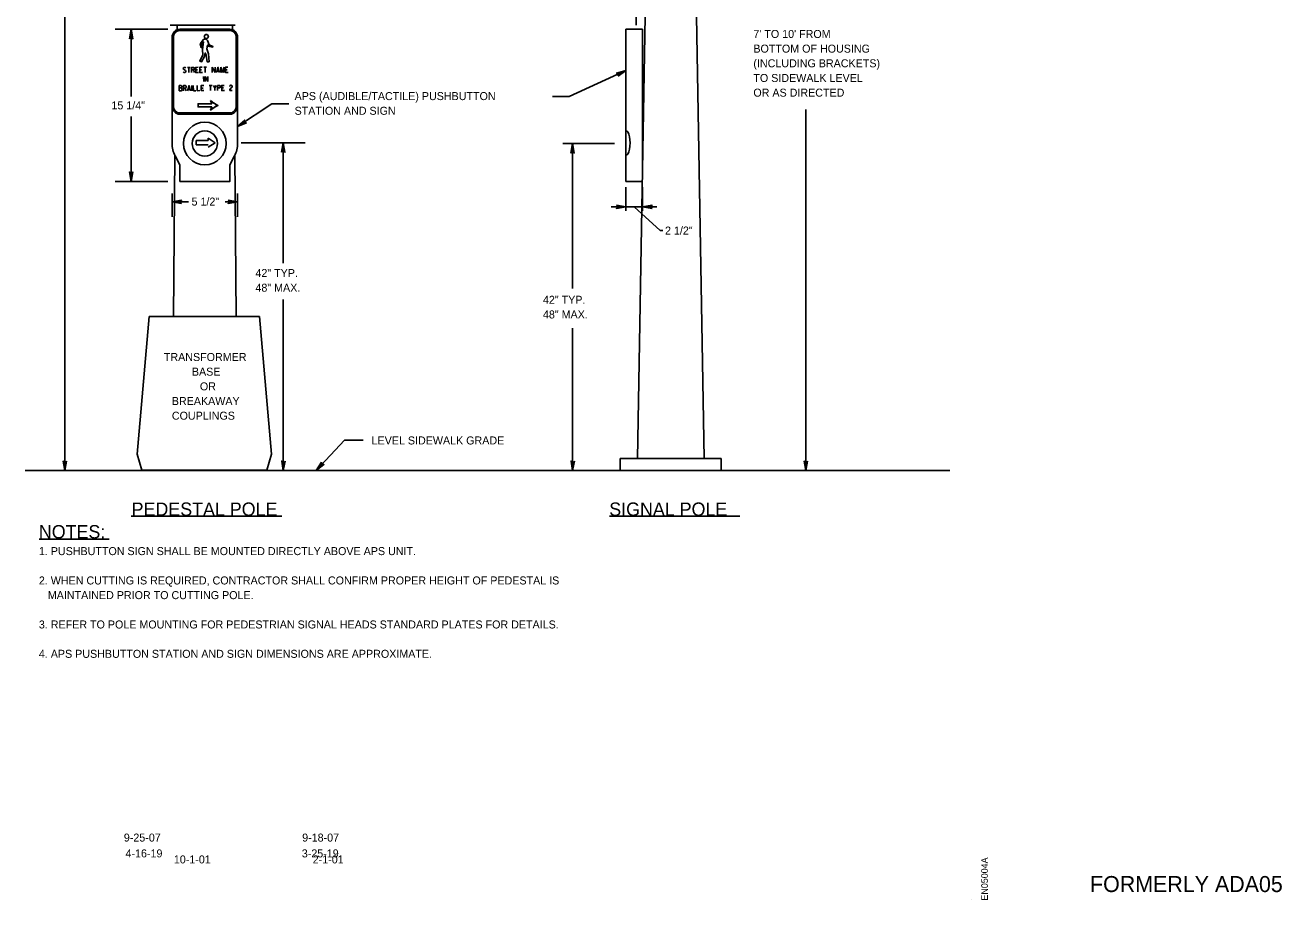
# Model space of a CAD drawing. Extents: x 12.4 to 21.9, y 5.3 to 15.4.
# Drawn here: x 12.52 to 21.94, y 5.33 to 11.89 of the extents above; entities that cross this region are included whole.
import ezdxf

# ---------------------------------------------------------------- set-up
doc = ezdxf.new("R2010")
doc.units = 0
for name, color, linetype in [('APPROVAL-OLD', 7, 'Continuous'), ('DETL-DIMS', 7, 'Continuous'), ('DETL-LINE', 7, 'Continuous'), ('DETL-NOTE', 7, 'Continuous'), ('DETL-TITL', 7, 'Continuous'), ('EN', 7, 'Continuous'), ('SIGN-FACE_P', 7, 'Continuous'), ('TTLB-TEXT', 7, 'Continuous')]:
    doc.layers.add(name, color=color, linetype=linetype)

msp = doc.modelspace()

# ---------------------------------------------------------------- linework, layer by layer
at = {"layer": 'DETL-DIMS'}
for p, q in [((12.8183, 12.1275), (12.8183, 8.549)), ((13.5893, 11.8579), (13.1959, 11.8579)), ((13.3153, 11.8579), (13.3023, 11.7865)), ((13.3023, 11.7865), (13.315, 11.7999)), ((13.315, 11.7999), (13.3275, 11.7863)), ((13.3153, 11.8579), (13.3275, 11.7863)), ((13.3153, 11.8579), (13.3153, 11.3531)), ((17.0236, 11.5479), (16.5976, 11.3538)), ((17.0236, 11.5479), (16.9534, 11.5293)), ((16.971, 11.5236), (16.9534, 11.5293)), ((17.0236, 11.5479), (16.9642, 11.5065)), ((16.9642, 11.5065), (16.971, 11.5236)), ((16.4721, 11.3538), (16.5976, 11.3538)), ((14.1129, 11.1281), (14.3704, 11.2982)), ((14.4959, 11.2982), (14.3704, 11.2982)), ((18.3716, 11.2568), (18.3716, 8.549)), ((13.3153, 11.2049), (13.3153, 10.7177)), ((14.1129, 11.1281), (14.1659, 11.1778)), ((14.1129, 11.1281), (14.1795, 11.1566)), ((14.1614, 11.1598), (14.1659, 11.1778)), ((14.1795, 11.1566), (14.1614, 11.1598)), ((14.6201, 11.0075), (14.1396, 11.0075)), ((14.4553, 11.0075), (14.4423, 10.9361)), ((14.4423, 10.9361), (14.455, 10.9495)), ((14.455, 10.9495), (14.4675, 10.9359)), ((14.4553, 11.0075), (14.4675, 10.9359)), ((14.4553, 11.0075), (14.4553, 10.1054)), ((16.9386, 11.0011), (16.5504, 11.0011)), ((16.6239, 11.0011), (16.6109, 10.9297)), ((16.6109, 10.9297), (16.6236, 10.9431)), ((16.6236, 10.9431), (16.6361, 10.9295)), ((16.6239, 11.0011), (16.6239, 9.9149)), ((16.6239, 11.0011), (16.6361, 10.9295)), ((13.3153, 10.7177), (13.3031, 10.7893)), ((13.3156, 10.7757), (13.3031, 10.7893)), ((13.3153, 10.7177), (13.3283, 10.7891)), ((13.3283, 10.7891), (13.3156, 10.7757)), ((13.5893, 10.7177), (13.1959, 10.7177)), ((17.0236, 10.6744), (17.0236, 10.4972)), ((17.1482, 10.6744), (17.1482, 10.4972)), ((13.6215, 10.6271), (13.6215, 10.453)), ((13.6215, 10.5643), (13.6931, 10.5765)), ((13.6215, 10.5643), (13.7457, 10.5643)), ((13.6215, 10.5643), (13.6929, 10.5513)), ((13.6795, 10.564), (13.6931, 10.5765)), ((13.6929, 10.5513), (13.6795, 10.564)), ((14.0203, 10.5643), (14.1129, 10.5643)), ((14.0549, 10.5646), (14.0413, 10.5521)), ((14.1129, 10.5643), (14.0413, 10.5521)), ((14.1129, 10.5643), (14.0415, 10.5773)), ((14.0415, 10.5773), (14.0549, 10.5646)), ((14.1129, 10.6271), (14.1129, 10.453)), ((16.9137, 10.5271), (17.2552, 10.5271)), ((16.9656, 10.5274), (16.952, 10.5149)), ((17.0236, 10.5271), (16.952, 10.5149)), ((17.0236, 10.5271), (16.9522, 10.5401)), ((16.9522, 10.5401), (16.9656, 10.5274)), ((17.2789, 10.3498), (17.0859, 10.5271)), ((17.1482, 10.5271), (17.2198, 10.5393)), ((17.1482, 10.5271), (17.2196, 10.5141)), ((17.2062, 10.5268), (17.2198, 10.5393)), ((17.2196, 10.5141), (17.2062, 10.5268)), ((17.2995, 10.3498), (17.2789, 10.3498)), ((14.4553, 9.8317), (14.4553, 8.549)), ((16.6239, 9.6167), (16.6239, 8.549)), ((14.9142, 8.7772), (14.702, 8.5511)), ((14.9143, 8.7772), (15.0537, 8.7772)), ((12.8183, 8.549), (12.8061, 8.6206)), ((12.8186, 8.607), (12.8061, 8.6206)), ((12.8183, 8.549), (12.8313, 8.6204)), ((12.8313, 8.6204), (12.8186, 8.607)), ((14.4553, 8.549), (14.4431, 8.6206)), ((14.4556, 8.607), (14.4431, 8.6206)), ((14.4553, 8.549), (14.4683, 8.6204)), ((14.4683, 8.6204), (14.4556, 8.607)), ((14.702, 8.551), (14.7414, 8.612)), ((14.702, 8.551), (14.7599, 8.5949)), ((14.7414, 8.612), (14.7415, 8.5935)), ((14.7415, 8.5935), (14.7599, 8.5949)), ((16.6239, 8.549), (16.6117, 8.6206)), ((16.6242, 8.607), (16.6117, 8.6206)), ((16.6239, 8.549), (16.6369, 8.6204)), ((16.6369, 8.6204), (16.6242, 8.607)), ((18.3716, 8.549), (18.3594, 8.6206)), ((18.3719, 8.607), (18.3594, 8.6206)), ((18.3716, 8.549), (18.3846, 8.6204)), ((18.3846, 8.6204), (18.3719, 8.607))]:
    msp.add_line(p, q, dxfattribs=at)
for points in [[(13.3023, 11.7865), (13.3153, 11.8579), (13.3275, 11.7863), (13.315, 11.7999)], [(16.9642, 11.5065), (17.0236, 11.5479), (16.9534, 11.5293), (16.971, 11.5236)], [(14.1795, 11.1566), (14.1129, 11.1281), (14.1659, 11.1778), (14.1614, 11.1598)], [(14.4423, 10.9361), (14.4553, 11.0075), (14.4675, 10.9359), (14.455, 10.9495)], [(16.6109, 10.9297), (16.6239, 11.0011), (16.6361, 10.9295), (16.6236, 10.9431)], [(13.3283, 10.7891), (13.3153, 10.7177), (13.3031, 10.7893), (13.3156, 10.7757)], [(13.6929, 10.5513), (13.6215, 10.5643), (13.6931, 10.5765), (13.6795, 10.564)], [(14.0415, 10.5773), (14.1129, 10.5643), (14.0413, 10.5521), (14.0549, 10.5646)], [(16.9522, 10.5401), (17.0236, 10.5271), (16.952, 10.5149), (16.9656, 10.5274)], [(17.2196, 10.5141), (17.1482, 10.5271), (17.2198, 10.5393), (17.2062, 10.5268)], [(12.8313, 8.6204), (12.8183, 8.549), (12.8061, 8.6206), (12.8186, 8.607)], [(14.4683, 8.6204), (14.4553, 8.549), (14.4431, 8.6206), (14.4556, 8.607)], [(14.7414, 8.612), (14.702, 8.551), (14.7599, 8.5949), (14.7415, 8.5935)], [(16.6369, 8.6204), (16.6239, 8.549), (16.6117, 8.6206), (16.6242, 8.607)], [(18.3846, 8.6204), (18.3716, 8.549), (18.3594, 8.6206), (18.3719, 8.607)]]:
    msp.add_lwpolyline(points, close=True, dxfattribs=at)
at = {"layer": 'DETL-LINE'}
for p, q in [((17.1109, 8.6403), (17.1939, 13.5402)), ((17.609, 8.6403), (17.526, 13.5402)), ((17.1001, 11.8893), (17.1001, 13.1019)), ((13.661, 11.8893), (13.6602, 11.8545)), ((14.0742, 11.8545), (14.0735, 11.8893)), ((17.0236, 11.2379), (17.0236, 11.8579)), ((17.0236, 11.8579), (17.1484, 11.8579)), ((17.1484, 10.8755), (17.1484, 11.8579)), ((13.6215, 11.28), (13.6215, 11.0024)), ((14.1129, 11.28), (14.1129, 11.0024)), ((17.0236, 11.2379), (17.0236, 10.7177)), ((13.6315, 9.7058), (13.6434, 10.9115)), ((14.0898, 10.9091), (14.0546, 10.8423)), ((14.1029, 9.7058), (14.0911, 10.9116)), ((17.0236, 10.7177), (17.1482, 10.7177)), ((13.45, 9.7058), (13.3603, 8.6727)), ((13.45, 9.7058), (14.278, 9.7058)), ((14.278, 9.7058), (14.3676, 8.6734)), ((13.3603, 8.6727), (13.3962, 8.5537)), ((14.3676, 8.6734), (14.3315, 8.5537)), ((16.9798, 8.549), (16.9798, 8.6403)), ((16.9798, 8.6403), (17.7377, 8.6403)), ((17.7377, 8.6403), (17.7377, 8.549)), ((12.5203, 8.549), (15.4543, 8.549)), ((13.3962, 8.5537), (14.3315, 8.5537)), ((15.2457, 8.549), (19.4518, 8.549))]:
    msp.add_line(p, q, dxfattribs=at)
at = {"layer": 'DETL-NOTE'}
msp.add_line((12.6261, 8.035), (13.1501, 8.035), dxfattribs=at)
at = {"layer": 'DETL-TITL'}
for p, q in [((13.3157, 8.2081), (14.4444, 8.2081)), ((16.8992, 8.2081), (17.8781, 8.2081))]:
    msp.add_line(p, q, dxfattribs=at)
at = {"layer": 'SIGN-FACE_P'}
for p, q in [((13.6084, 11.8893), (14.0935, 11.8893)), ((13.6215, 11.7996), (13.6215, 11.28)), ((13.6313, 11.7996), (13.6313, 11.28)), ((14.0546, 11.8579), (13.6799, 11.8579)), ((14.0546, 11.8482), (13.6799, 11.8482)), ((13.8561, 11.7809), (13.8317, 11.7493)), ((13.8561, 11.7809), (13.8658, 11.7843)), ((13.8658, 11.7843), (13.8687, 11.7882)), ((13.8792, 11.7855), (13.8788, 11.7815)), ((13.8788, 11.7815), (13.8877, 11.7743)), ((13.8877, 11.7743), (13.8988, 11.7418)), ((14.1032, 11.28), (14.1032, 11.7996)), ((14.1129, 11.28), (14.1129, 11.7996)), ((13.8317, 11.7493), (13.8398, 11.7204)), ((13.8398, 11.7204), (13.8458, 11.7219)), ((13.843, 11.7484), (13.8584, 11.7628)), ((13.8458, 11.7219), (13.843, 11.7484)), ((13.8524, 11.7273), (13.8499, 11.7031)), ((13.8525, 11.6662), (13.8499, 11.7031)), ((13.8549, 11.744), (13.8524, 11.7273)), ((13.8584, 11.7628), (13.8549, 11.744)), ((13.8709, 11.6815), (13.8651, 11.6548)), ((13.8784, 11.6651), (13.8709, 11.6815)), ((13.8878, 11.7402), (13.8811, 11.7115)), ((13.8811, 11.7115), (13.8945, 11.6747)), ((13.8929, 11.7316), (13.8878, 11.7402)), ((13.9245, 11.7229), (13.8929, 11.7316)), ((13.8988, 11.7418), (13.9276, 11.7287)), ((13.9276, 11.7287), (13.9245, 11.7229)), ((13.8293, 11.62), (13.8525, 11.6662)), ((13.8418, 11.6134), (13.8293, 11.62)), ((13.8651, 11.6548), (13.8418, 11.6134)), ((13.8838, 11.6147), (13.8784, 11.6651)), ((13.8988, 11.6151), (13.8838, 11.6147)), ((13.8988, 11.6151), (13.8838, 11.6151)), ((13.8945, 11.6747), (13.8988, 11.6151)), ((13.7072, 11.5696), (13.7049, 11.5647)), ((13.7049, 11.5647), (13.7049, 11.5629)), ((13.7049, 11.5629), (13.7075, 11.5583)), ((13.7092, 11.5347), (13.705, 11.5381)), ((13.7126, 11.5724), (13.7072, 11.5696)), ((13.7075, 11.5583), (13.7226, 11.5492)), ((13.712, 11.5335), (13.7092, 11.5347)), ((13.7183, 11.5336), (13.712, 11.5335)), ((13.7186, 11.5725), (13.7126, 11.5724)), ((13.7227, 11.5363), (13.7183, 11.5336)), ((13.7238, 11.5697), (13.7186, 11.5725)), ((13.7226, 11.5492), (13.7252, 11.5449)), ((13.725, 11.5412), (13.7227, 11.5363)), ((13.7252, 11.5449), (13.725, 11.5412)), ((13.736, 11.5725), (13.7576, 11.5726)), ((13.7469, 11.5726), (13.7471, 11.5337)), ((13.7813, 11.5537), (13.7889, 11.5339)), ((13.7995, 11.5535), (13.813, 11.5536)), ((13.8291, 11.5537), (13.8426, 11.5537)), ((13.8585, 11.4661), (13.8583, 11.505)), ((13.8586, 11.5731), (13.8802, 11.5732)), ((13.8693, 11.4662), (13.8692, 11.5051)), ((13.8692, 11.5051), (13.8899, 11.4663)), ((13.8696, 11.5731), (13.8697, 11.5342)), ((13.8899, 11.4663), (13.8897, 11.5052)), ((13.9233, 11.5345), (13.9231, 11.5734)), ((13.9231, 11.5734), (13.9438, 11.5346)), ((13.9438, 11.5346), (13.9436, 11.5735)), ((13.9734, 11.5439), (13.957, 11.5438)), ((13.9866, 11.5348), (13.9865, 11.5737)), ((13.9865, 11.5737), (13.9991, 11.5348)), ((13.9991, 11.5348), (14.0109, 11.5738)), ((14.0109, 11.5738), (14.0111, 11.5349)), ((14.0218, 11.5545), (14.0354, 11.5546)), ((13.6886, 11.4362), (13.6754, 11.4362)), ((13.6754, 11.4362), (13.6755, 11.3973)), ((13.6903, 11.4185), (13.6755, 11.4184)), ((13.6931, 11.4335), (13.6886, 11.4362)), ((13.6903, 11.4185), (13.6931, 11.4221)), ((13.6945, 11.4145), (13.6903, 11.4185)), ((13.6904, 11.3973), (13.6945, 11.4001)), ((13.6944, 11.4283), (13.6931, 11.4335)), ((13.6931, 11.4221), (13.6944, 11.4267)), ((13.6944, 11.4267), (13.6944, 11.4283)), ((13.696, 11.4099), (13.6945, 11.4145)), ((13.6945, 11.4001), (13.6961, 11.4053)), ((13.6961, 11.4053), (13.696, 11.4099)), ((13.7196, 11.4174), (13.7273, 11.3975)), ((13.7568, 11.4068), (13.7404, 11.4067)), ((13.7701, 11.3977), (13.7699, 11.4366)), ((13.7808, 11.4366), (13.781, 11.3977)), ((13.781, 11.3977), (13.7997, 11.3978)), ((13.8104, 11.4368), (13.8106, 11.3979)), ((13.8106, 11.3979), (13.8293, 11.398)), ((13.8401, 11.4176), (13.8537, 11.4177)), ((13.8993, 11.4372), (13.9209, 11.4373)), ((13.9102, 11.4372), (13.9104, 11.3983)), ((13.942, 11.4187), (13.9421, 11.3985)), ((13.9632, 11.4374), (13.9764, 11.4375)), ((13.9633, 11.3986), (13.9632, 11.4374)), ((13.9765, 11.4185), (13.9632, 11.4185)), ((13.9764, 11.4375), (13.9803, 11.436)), ((13.9807, 11.4201), (13.9765, 11.4185)), ((13.9803, 11.436), (13.9837, 11.4299)), ((13.9838, 11.4262), (13.9807, 11.4201)), ((13.9837, 11.4299), (13.9838, 11.4262)), ((13.9944, 11.4183), (14.0079, 11.4184)), ((14.0536, 11.4299), (14.0546, 11.4336)), ((14.0548, 11.4057), (14.0537, 11.4026)), ((14.0537, 11.4026), (14.0537, 11.399)), ((14.0537, 11.399), (14.0725, 11.399)), ((14.0546, 11.4336), (14.0575, 11.4366)), ((14.0649, 11.418), (14.0548, 11.4057)), ((14.0575, 11.4366), (14.0614, 11.4379)), ((14.0614, 11.4379), (14.0642, 11.4379)), ((14.0642, 11.4379), (14.0682, 11.4367)), ((14.0713, 11.4238), (14.0649, 11.418)), ((14.0682, 11.4367), (14.071, 11.4333)), ((14.071, 11.4333), (14.0723, 11.43)), ((14.0724, 11.4266), (14.0713, 11.4238)), ((14.0723, 11.43), (14.0724, 11.4266)), ((13.6755, 11.3973), (13.6904, 11.3973)), ((13.9189, 11.2995), (13.9102, 11.3234)), ((13.6799, 11.2314), (14.0546, 11.2314)), ((13.6799, 11.2217), (14.0546, 11.2217)), ((13.9189, 11.2995), (13.8162, 11.2995)), ((13.8162, 11.2764), (13.8162, 11.2995)), ((13.9189, 11.2764), (13.8162, 11.2764)), ((13.9103, 11.2519), (13.9189, 11.2764)), ((13.8016, 10.9917), (13.8016, 11.0242)), ((13.8016, 11.0242), (13.892, 11.0242)), ((13.892, 11.0242), (13.892, 11.0421)), ((13.892, 11.0421), (13.945, 11.0075)), ((13.892, 10.9917), (13.8016, 10.9917)), ((13.945, 11.0075), (13.892, 10.9732)), ((13.6446, 10.9091), (13.6799, 10.8423))]:
    msp.add_line(p, q, dxfattribs=at)
for points in [[(13.8687, 11.7882), (13.8711, 11.7861), (13.8734, 11.7852), (13.8765, 11.7852), (13.8792, 11.7855), (13.8788, 11.7815), (13.8877, 11.7743), (13.8988, 11.7418), (13.9276, 11.7287), (13.9245, 11.7229), (13.8929, 11.7316), (13.8878, 11.7402), (13.8811, 11.7115), (13.8945, 11.6747), (13.8988, 11.6151), (13.8838, 11.6147), (13.8784, 11.6651), (13.8709, 11.6815), (13.8651, 11.6548), (13.8418, 11.6134), (13.8293, 11.62), (13.8525, 11.6662), (13.8499, 11.7031), (13.8584, 11.7628), (13.843, 11.7484), (13.8458, 11.7219), (13.8398, 11.7204), (13.8317, 11.7493), (13.8561, 11.7809), (13.8658, 11.7843)], [(13.9102, 11.3234), (13.9242, 11.312), (13.9343, 11.3047), (13.9438, 11.2994), (13.9533, 11.2936), (13.9655, 11.2877), (13.9573, 11.2838), (13.946, 11.278), (13.9368, 11.2725), (13.9263, 11.2648), (13.9193, 11.2602), (13.9103, 11.2519), (13.9189, 11.2764), (13.8162, 11.2764), (13.8162, 11.2995), (13.9189, 11.2995)]]:
    msp.add_lwpolyline(points, close=True, dxfattribs=at)
for points in [[(13.7684, 11.5338), (13.7682, 11.5727), (13.7815, 11.5727), (13.7854, 11.5712), (13.7888, 11.5651), (13.7888, 11.5614), (13.7857, 11.5553), (13.7816, 11.5537), (13.7683, 11.5537)], [(13.8184, 11.5729), (13.7994, 11.5728), (13.7995, 11.5339), (13.8198, 11.534)], [(13.848, 11.573), (13.829, 11.5729), (13.8292, 11.5341), (13.8495, 11.5342)], [(13.9544, 11.5346), (13.9652, 11.5736), (13.976, 11.5347)], [(14.0408, 11.5739), (14.0218, 11.5738), (14.0219, 11.5349), (14.0422, 11.535)], [(13.7067, 11.3974), (13.7065, 11.4363), (13.7198, 11.4364), (13.7237, 11.4348), (13.7271, 11.4287), (13.7271, 11.4251), (13.724, 11.4189), (13.7199, 11.4174), (13.7066, 11.4173)], [(13.7379, 11.3975), (13.7486, 11.4365), (13.7595, 11.3976)], [(13.859, 11.437), (13.84, 11.4369), (13.8402, 11.398), (13.8605, 11.3981)], [(13.9315, 11.4373), (13.942, 11.4187), (13.9523, 11.4374)], [(14.0133, 11.4377), (13.9943, 11.4376), (13.9945, 11.3987), (14.0148, 11.3988)], [(14.0546, 10.8423), (14.0546, 10.7177), (13.6799, 10.7177), (13.6799, 10.8423)]]:
    msp.add_lwpolyline(points, dxfattribs=at)
for centre, radius in [((13.8782, 11.8038), 0.0153), ((13.8782, 11.8038), 0.0151), ((13.8672, 11.0021), 0.1598), ((13.8673, 11.0021), 0.0941)]:
    msp.add_circle(centre, radius, dxfattribs=at)
for centre, radius, start, end in [((13.6799, 11.7996), 0.0583, 90, 180), ((13.6799, 11.7996), 0.0486, 90, 180), ((13.8761, 11.7951), 0.0102, 222.7791, 288.23139), ((14.0545, 11.7996), 0.0583, 0, 90), ((14.0545, 11.7996), 0.0486, 0, 90), ((14.0517, 11.482), 0.2125, 228.26105, 246.08553), ((13.6799, 11.28), 0.0583, 180, 270), ((13.6799, 11.28), 0.0486, 180, 270), ((14.0521, 11.0936), 0.2125, 114.04556, 131.87004), ((14.0545, 11.28), 0.0583, 270, 0), ((14.0545, 11.28), 0.0486, 270, 0), ((13.8215, 11.0024), 0.2, 180, 207.81064), ((13.9129, 11.0024), 0.2, 332.20103, 0)]:
    msp.add_arc(centre, radius, start, end, dxfattribs=at)
msp.add_ellipse((17.0244, 11.0056), major_axis=(0, 0.0906), ratio=0.335171, start_param=3.115249, end_param=6.309529, dxfattribs=at)
at = {"layer": 'TTLB-TEXT'}
msp.add_line((19.6128, 5.3308), (19.6128, 5.3308), dxfattribs=at)

# ---------------------------------------------------------------- texts
at = {"layer": 'APPROVAL-OLD'}
for s, p in [('10-1-01', (13.6349, 5.6042)), ('2-1-01', (14.6759, 5.6042))]:
    msp.add_text(s, height=0.06, dxfattribs=at).set_placement(p)
at = {"layer": 'DETL-NOTE'}
for s, height, p in [("7' TO 10' FROM", 0.06, (17.9786, 11.7931)), ('BOTTOM OF HOUSING', 0.06, (17.9786, 11.6831)), ('(INCLUDING BRACKETS)', 0.06, (17.9786, 11.5731)), ('TO SIDEWALK LEVEL', 0.06, (17.9786, 11.4631)), ('OR AS DIRECTED', 0.06, (17.9786, 11.3531)), ('15 1/4"', 0.06, (13.167, 11.2578)), ('APS (AUDIBLE/TACTILE) PUSHBUTTON', 0.06, (14.5398, 11.3272)), ('STATION AND SIGN', 0.06, (14.5398, 11.2172)), ('5 1/2"', 0.06, (13.7676, 10.5363)), ('2 1/2"', 0.06, (17.3165, 10.3191)), ('42" TYP.', 0.06, (14.2465, 10.0006)), ('48" MAX.', 0.06, (14.2465, 9.8906)), ('42" TYP.', 0.06, (16.4014, 9.8)), ('48" MAX.', 0.06, (16.4014, 9.69)), ('TRANSFORMER', 0.06, (13.5601, 9.371)), ('BASE', 0.06, (13.7702, 9.261)), ('OR', 0.06, (13.8301, 9.151)), ('BREAKAWAY', 0.06, (13.6197, 9.041)), ('COUPLINGS', 0.06, (13.6201, 8.931)), ('LEVEL SIDEWALK GRADE', 0.06, (15.117, 8.7453)), ('NOTES:', 0.1, (12.6233, 8.0407)), ('1. PUSHBUTTON SIGN SHALL BE MOUNTED DIRECTLY ABOVE APS UNIT.', 0.06, (12.6233, 7.9157)), ('2. WHEN CUTTING IS REQUIRED, CONTRACTOR SHALL CONFIRM PROPER HEIGHT OF PEDESTAL IS ', 0.06, (12.6233, 7.6957)), ('   MAINTAINED PRIOR TO CUTTING POLE.', 0.06, (12.6233, 7.5857)), ('3. REFER TO POLE MOUNTING FOR PEDESTRIAN SIGNAL HEADS STANDARD PLATES FOR DETAILS.', 0.06, (12.6233, 7.3657)), ('4. APS PUSHBUTTON STATION AND SIGN DIMENSIONS ARE APPROXIMATE.', 0.06, (12.6233, 7.1457))]:
    msp.add_text(s, height=height, dxfattribs=at).set_placement(p)
at = {"layer": 'DETL-TITL'}
for s, p in [('PEDESTAL POLE', (13.3185, 8.2101)), ('SIGNAL POLE', (16.8985, 8.2101))]:
    msp.add_text(s, height=0.1, dxfattribs=at).set_placement(p)
at = {"layer": 'EN'}
msp.add_text('EN05004A', height=0.05, rotation=90, dxfattribs=at).set_placement((19.7363, 5.3256))
at = {"layer": 'TTLB-TEXT'}
for s, height, p in [('9-25-07', 0.06, (13.2601, 5.7679)), ('9-18-07', 0.06, (14.5968, 5.7679)), ('4-16-19', 0.06, (13.2727, 5.6493)), ('3-25-19', 0.06, (14.594, 5.6493)), ('FORMERLY ADA05', 0.12, (20.5019, 5.3895))]:
    msp.add_text(s, height=height, dxfattribs=at).set_placement(p)

doc.saveas('drawing.dxf')
